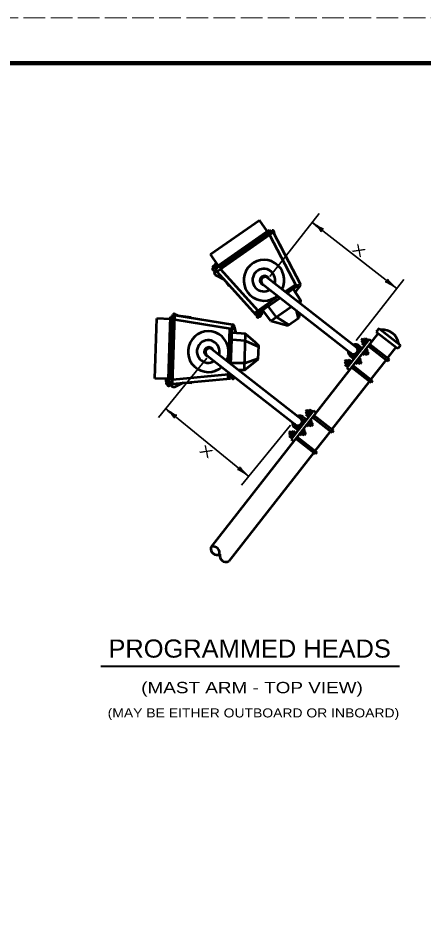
# Model space of a CAD drawing. Extents: x -286 to 394, y -156 to 284.
# Drawn here: x 126.4 to 216, y 87.7 to 284.5 of the extents above; entities that cross this region are included whole.
import ezdxf
from ezdxf.enums import TextEntityAlignment as Align

# ---------------------------------------------------------------- set-up
doc = ezdxf.new("R2010")
doc.units = 0
doc.header["$LTSCALE"] = 0.8
doc.linetypes.add('LONG_DASHED', pattern=[7.5, 6, -1.5])
doc.layers.add('1', color=7, linetype='Continuous', lineweight=53)
doc.layers.add('61', color=7, linetype='Continuous', lineweight=35)

msp = doc.modelspace()

# ---------------------------------------------------------------- linework, layer by layer
at = {"layer": '1', "lineweight": 35}
for p, q in [((192.9885, 241.2487), (182.1, 227.312)), ((191.4423, 239.2697), (210.1276, 224.6712)), ((211.6737, 226.6502), (201.1274, 213.1514)), ((157.4704, 196.1745), (168.1396, 209.2607)), ((159.0574, 198.121), (177.4352, 183.1374)), ((175.8484, 181.1909), (186.673, 194.4676))]:
    msp.add_line(p, q, dxfattribs=at)
at = {"layer": '1'}
for p, q in [((168.9452, 232.223), (179.8082, 239.7817)), ((181.5218, 237.3192), (179.8082, 239.7817)), ((170.2889, 228.3437), (182.8359, 237.0743)), ((170.6522, 229.7562), (181.9386, 237.6095)), ((171.143, 229.4887), (182.6347, 237.4847)), ((181.9386, 237.6095), (182.2242, 237.1989)), ((182.0084, 236.4987), (187.9568, 225.1043)), ((182.8359, 237.0743), (188.7847, 225.6803)), ((182.9205, 237.3707), (183.1277, 236.5162)), ((183.1277, 236.5162), (184.6073, 233.9458)), ((170.6587, 229.7608), (168.9452, 232.223)), ((169.8214, 229.2523), (169.5507, 229.1807)), ((170.2569, 229.0472), (169.5811, 229.3725)), ((170.3805, 229.2647), (169.6897, 229.5973)), ((169.9717, 229.1781), (169.8678, 228.9185)), ((169.9559, 229.4749), (169.8867, 229.7459)), ((170.0832, 229.4082), (170.2589, 229.6254)), ((170.3699, 228.4001), (179.0186, 218.8265)), ((171.1457, 228.9399), (179.4239, 219.7762)), ((170.1608, 227.5875), (172.0078, 226.614)), ((172.0078, 226.614), (173.0461, 225.1295)), ((181.4162, 227.1339), (201.3163, 211.5916)), ((180.3407, 225.7569), (200.2382, 210.2128)), ((185.4593, 223.9762), (187.7235, 225.5517)), ((185.8721, 223.6538), (187.9568, 225.1043)), ((188.8565, 222.0757), (187.2297, 224.5965)), ((188.5697, 225.0199), (187.6993, 223.869)), ((178.5965, 219.2007), (183.9578, 222.9313)), ((178.9342, 218.8265), (184.3704, 222.6089)), ((186.2382, 223.3678), (185.9982, 223.7399)), ((183.5209, 218.3632), (181.7223, 220.7643)), ((182.2897, 217.5062), (186.8448, 220.6758)), ((159.6772, 204.6498), (160.1542, 218.3912)), ((160.1542, 218.3912), (160.654, 218.3738)), ((160.1853, 204.8822), (160.6713, 218.8738)), ((160.5902, 203.5123), (161.1204, 218.7888)), ((160.9338, 219.0342), (161.7422, 218.6879)), ((161.1204, 218.7888), (173.8066, 216.7227)), ((161.7422, 218.6879), (164.6864, 218.332)), ((179.5824, 218.8785), (179.3481, 218.7266)), ((179.3996, 219.1328), (179.849, 218.5328)), ((179.5997, 219.2823), (180.0494, 218.6826)), ((179.6849, 218.7447), (179.6668, 218.4657)), ((179.7873, 219.0319), (179.9663, 219.2463)), ((179.877, 218.9202), (180.1561, 218.9043)), ((182.2897, 217.5062), (180.4912, 219.9077)), ((182.2897, 217.5062), (185.5074, 219.7455)), ((187.925, 219.832), (188.3123, 218.0422)), ((188.6141, 219.2937), (188.5174, 218.1855)), ((156.6793, 204.7616), (157.1387, 217.9876)), ((160.1368, 217.8837), (157.1387, 217.9876)), ((161.0853, 217.7815), (173.7717, 215.7147)), ((182.2897, 217.5062), (186.0552, 216.4717)), ((183.5209, 218.3632), (186.2604, 216.6146)), ((186.0552, 216.4717), (188.5174, 218.1855)), ((206.0048, 214.7497), (169.0651, 167.469)), ((173.1147, 211.2112), (173.2738, 215.7961)), ((173.6198, 211.3482), (173.7717, 215.7147)), ((176.7353, 214.6199), (173.7425, 214.8283)), ((174.2065, 216.1548), (174.6062, 214.7682)), ((206.2262, 215.8456), (205.6107, 215.0575)), ((205.6107, 215.0575), (210.3388, 211.3637)), ((206.2262, 215.8456), (210.9543, 212.1517)), ((176.6834, 213.1202), (173.6901, 213.3291)), ((176.6834, 213.1204), (179.6382, 211.767)), ((178.8171, 212.7587), (179.6463, 212.0172)), ((202.5814, 213.617), (202.2736, 213.223)), ((202.2736, 213.223), (203.2587, 212.4534)), ((203.2556, 213.6677), (202.3876, 212.5566)), ((202.3876, 212.5566), (202.9786, 212.0949)), ((202.6028, 213.4416), (202.4489, 213.2446)), ((202.7784, 213.4631), (202.4706, 213.0691)), ((202.5814, 213.617), (203.5666, 212.8474)), ((202.7999, 213.2877), (202.646, 213.0907)), ((203.2556, 213.6677), (203.8466, 213.2061)), ((204.0283, 213.4384), (204.6195, 212.9766)), ((169.1036, 211.3732), (189.0034, 195.8311)), ((173.0142, 208.3189), (173.1145, 211.2112)), ((173.5016, 207.9382), (173.62, 211.3482)), ((176.4579, 206.6245), (176.6504, 212.1706)), ((176.4579, 206.6245), (176.5937, 210.5425)), ((179.5427, 209.0189), (179.6463, 212.0172)), ((201.5034, 211.596), (202.1774, 211.0693)), ((201.7392, 212.0463), (202.4852, 211.4634)), ((202.7685, 210.6075), (203.5565, 209.9918)), ((203.7167, 211.009), (202.9162, 209.9844)), ((203.0763, 211.0015), (203.8643, 210.3858)), ((203.3227, 211.3167), (203.7167, 211.009)), ((203.6672, 210.5398), (203.3594, 210.1458)), ((203.8499, 211.9916), (208.1839, 208.6057)), ((204.1577, 212.3856), (208.4917, 208.9997)), ((209.9447, 211.6715), (208.0977, 209.3075)), ((210.9543, 212.1517), (210.3388, 211.3637)), ((168.0279, 209.9964), (187.9253, 194.4524)), ((176.4579, 206.6245), (179.5427, 209.0189)), ((176.5097, 208.1238), (179.5513, 209.2689)), ((198.8875, 208.889), (198.5797, 208.495)), ((199.5617, 208.9398), (198.6937, 207.8286)), ((198.9089, 208.7136), (198.755, 208.5166)), ((199.0845, 208.7351), (198.7767, 208.3411)), ((198.8875, 208.889), (199.8727, 208.1193)), ((199.106, 208.5597), (198.9521, 208.3627)), ((200.5653, 209.0058), (199.1032, 207.1342)), ((199.5617, 208.9398), (200.1527, 208.478)), ((199.8985, 209.6809), (200.6402, 209.1016)), ((199.9195, 210.462), (200.0032, 210.3228)), ((200.2063, 210.0749), (200.9479, 209.4956)), ((201.2312, 208.6398), (202.0193, 208.0244)), ((202.1793, 209.0413), (201.379, 208.0169)), ((201.5391, 209.0338), (202.327, 208.4183)), ((201.7853, 209.3491), (202.1793, 209.0413)), ((202.1299, 208.5722), (201.8222, 208.1783)), ((202.5222, 210.2922), (202.9162, 209.9844)), ((203.4762, 210.4987), (203.3531, 210.341)), ((203.6733, 210.3448), (203.5502, 210.1871)), ((203.8643, 210.3858), (203.5565, 209.9918)), ((207.7899, 208.9135), (204.4038, 204.5794)), ((208.4917, 208.9997), (208.1839, 208.6057)), ((176.5097, 208.1238), (173.5097, 208.1229)), ((176.4579, 206.6245), (175.184, 206.6242)), ((198.5797, 208.495), (199.5649, 207.7253)), ((198.6937, 207.8286), (199.2848, 207.3668)), ((199.1032, 207.1342), (199.6942, 206.6725)), ((200.1559, 207.2635), (204.49, 203.8776)), ((200.4638, 207.6576), (204.7978, 204.2716)), ((200.985, 208.3247), (201.379, 208.0169)), ((201.939, 208.5311), (201.8159, 208.3735)), ((202.1361, 208.3772), (202.013, 208.2196)), ((202.327, 208.4183), (202.0193, 208.0244)), ((159.6773, 204.6577), (156.6793, 204.7616)), ((160.5935, 203.6112), (173.3922, 204.7927)), ((160.6263, 204.5557), (172.9232, 205.6907)), ((172.8902, 204.7463), (172.9393, 206.1596)), ((173.3922, 204.7927), (173.4265, 205.779)), ((173.4237, 205.2858), (174.0577, 205.2859)), ((173.424, 205.5356), (173.7378, 205.5358)), ((173.7368, 205.2798), (173.718, 205.0011)), ((173.9054, 205.2817), (174.1179, 205.0999)), ((159.485, 203.9238), (159.2266, 204.0307)), ((159.9078, 204.1377), (159.2275, 203.784)), ((160.0078, 203.9083), (159.3424, 203.5623)), ((159.5826, 203.6827), (159.4777, 203.4232)), ((159.6147, 203.9857), (159.5462, 204.2565)), ((159.7321, 203.7585), (159.8777, 203.5198)), ((161.1188, 202.9567), (163.005, 203.8518)), ((163.005, 203.8518), (164.8156, 203.7934)), ((204.096, 204.1854), (195.7846, 193.5472)), ((204.7978, 204.2716), (204.49, 203.8776)), ((190.2685, 197.8566), (189.9607, 197.4626)), ((189.9607, 197.4626), (190.9458, 196.693)), ((190.9427, 197.9073), (190.0747, 196.7962)), ((190.0747, 196.7962), (190.6657, 196.3345)), ((190.2899, 197.6812), (190.136, 197.4842)), ((190.4655, 197.7027), (190.1577, 197.3087)), ((190.2685, 197.8566), (191.2537, 197.087)), ((190.487, 197.5272), (190.3331, 197.3303)), ((190.9427, 197.9073), (191.5337, 197.4457)), ((191.7154, 197.678), (192.3063, 197.2164)), ((189.1905, 195.8356), (189.8645, 195.3089)), ((189.4262, 196.2859), (190.1723, 195.703)), ((190.4556, 194.8471), (191.2436, 194.2314)), ((191.4038, 195.2486), (190.6033, 194.224)), ((190.7634, 195.2411), (191.5514, 194.6254)), ((191.0097, 195.5563), (191.4038, 195.2486)), ((191.3543, 194.7794), (191.0465, 194.3854)), ((191.537, 196.2312), (195.871, 192.8452)), ((191.8448, 196.6252), (196.1788, 193.2392)), ((186.5746, 193.1286), (186.2668, 192.7346)), ((187.2488, 193.1793), (186.3808, 192.0682)), ((186.596, 192.9532), (186.4421, 192.7562)), ((186.7716, 192.9747), (186.4638, 192.5807)), ((186.5746, 193.1286), (187.5598, 192.3589)), ((188.2524, 193.2454), (186.7902, 191.3738)), ((187.2488, 193.1793), (187.8398, 192.7176)), ((187.5856, 193.9205), (188.3272, 193.3412)), ((187.8934, 194.3145), (188.635, 193.7352)), ((188.9183, 192.8794), (189.7064, 192.264)), ((189.8664, 193.2809), (189.0661, 192.2565)), ((189.2262, 193.2734), (190.0141, 192.6579)), ((189.4724, 193.5887), (189.8664, 193.2809)), ((189.817, 192.8118), (189.5093, 192.4179)), ((190.2093, 194.5318), (190.6033, 194.224)), ((191.1633, 194.7382), (191.0402, 194.5806)), ((191.3604, 194.5843), (191.2372, 194.4267)), ((191.5514, 194.6254), (191.2436, 194.2314)), ((195.4767, 193.1532), (192.0907, 188.8192)), ((196.1788, 193.2392), (195.871, 192.8452)), ((186.2668, 192.7346), (187.252, 191.9649)), ((186.3808, 192.0682), (186.9718, 191.6064)), ((186.7931, 192.7993), (186.6392, 192.6022)), ((186.7902, 191.3738), (187.381, 190.9123)), ((187.843, 191.5031), (192.1771, 188.1172)), ((188.1509, 191.8972), (192.4849, 188.5112)), ((188.6721, 192.5642), (189.0661, 192.2565)), ((189.6261, 192.7707), (189.503, 192.6131)), ((189.8232, 192.6167), (189.7001, 192.4592)), ((190.0141, 192.6579), (189.7064, 192.264)), ((191.7827, 188.4253), (173.0051, 164.3907)), ((192.4849, 188.5112), (192.1771, 188.1172))]:
    msp.add_line(p, q, dxfattribs=at)
at = {"layer": '1', "lineweight": 40}
msp.add_line((144.7021, 141.212), (210.74, 141.212), dxfattribs=at)
at = {"layer": '1'}
for points in [[(170.6522, 229.7562), (169.8256, 228.2606), (170.2889, 228.3437)], [(188.3468, 221.721), (188.8565, 222.0757), (188.7951, 221.3709)], [(176.6505, 212.1706), (176.7353, 214.6199), (178.817, 212.7586)], [(204.0283, 213.4384), (202.5662, 211.5669), (200.5653, 209.0058)], [(159.6772, 204.6498), (160.379, 203.0917), (160.5902, 203.5123)], [(191.7154, 197.678), (190.2532, 195.8065), (188.2524, 193.2454)]]:
    msp.add_lwpolyline(points, dxfattribs=at)
for centre in [(182.6388, 237.248), (188.3776, 225.3079), (160.8632, 218.7351), (173.8608, 216.1736)]:
    msp.add_circle(centre, 0.1017, dxfattribs=at)
for centre, radius, start, end in [((182.7109, 237.2676), 0.2301, 302.89292, 109.35881), ((180.8013, 226.4584), 4.5, 333.68871, 311.29261), ((169.6271, 228.9502), 0.243, 108.32387, 352.5212), ((169.6268, 229.489), 0.1254, 59.95241, 248.62496), ((170.4196, 228.1365), 0.6069, 168.18066, 244.76157), ((170.1125, 229.8089), 0.2347, 308.58522, 195.64631), ((171.0092, 229.827), 0.364, 191.23275, 291.55987), ((180.7701, 226.5032), 2.5, 342.98256, 302.06743), ((180.8989, 226.4279), 1.0052, 23.95779, 262.9292), ((181.0541, 226.3131), 0.8972, 66.19313, 220.65033), ((188.3191, 225.4666), 0.5121, 224.97004, 24.69248), ((160.8908, 218.8046), 0.2301, 356.07364, 162.53953), ((179.4259, 218.4962), 0.243, 108.60971, 352.80704), ((179.9546, 218.6), 0.1254, 212.50594, 41.17849), ((180.1747, 219.1382), 0.2347, 265.48459, 152.54568), ((173.6988, 216.2219), 0.5121, 278.15075, 77.87319), ((168.4964, 210.6907), 4.5, 334.34216, 311.30255), ((206.9745, 211.9302), 3.6248, 8.39612, 95.60566), ((168.4647, 210.7351), 2.5, 343.63601, 302.72088), ((168.5943, 210.6613), 1.0052, 24.61124, 263.58265), ((168.7508, 210.5483), 0.8972, 66.84658, 221.30378), ((200.5605, 210.6003), 1.133, 168.40396, 234.24561), ((200.7734, 210.9049), 1.0052, 202.49407, 81.46547), ((200.6215, 211.024), 0.8972, 244.77294, 39.23013), ((201.0124, 211.1823), 1.133, 49.4358, 115.27744), ((159.8344, 204.978), 0.364, 244.41346, 344.74058), ((173.9491, 204.9253), 0.243, 161.79042, 45.98775), ((159.3115, 204.2492), 0.2347, 1.76594, 248.82702), ((159.2766, 203.6687), 0.1254, 113.13313, 301.80568), ((159.7081, 203.3461), 0.243, 161.50458, 45.70191), ((160.8344, 203.4928), 0.6069, 221.36137, 297.94229), ((188.2476, 194.8399), 1.133, 168.40396, 234.24561), ((188.4605, 195.1445), 1.0052, 202.49407, 81.46547), ((188.3085, 195.2636), 0.8972, 244.77294, 39.23013), ((188.6995, 195.4219), 1.133, 49.4358, 115.27744), ((170.4231, 167.1768), 1.3891, 167.85849, 296.14028), ((169.5278, 166.2058), 1.4466, 343.66244, 103.21923), ((172.3723, 165.6111), 1.3747, 166.59364, 297.40514)]:
    msp.add_arc(centre, radius, start, end, dxfattribs=at)
at = {"layer": '1', "lineweight": 35}
for centre, major_axis, ratio, start_param, end_param in [((192.195, 238.4132), (1.276, -1.2198), 0.07063, 6.28230741, 8.55970261), ((192.195, 238.4132), (1.276, -1.2198), 0.07063, 6.28230741, 8.55970261), ((192.4723, 238.8157), (-1.5033, 0.9763), 0.122415, 0.89635335, 3.14159265), ((192.4723, 238.8157), (-1.5033, 0.9763), 0.122415, 0.89635335, 3.14159265), ((209.3749, 225.5278), (-1.276, 1.2198), 0.07063, 6.28230741, 8.55970261), ((209.3749, 225.5278), (-1.276, 1.2198), 0.07063, 6.28230741, 8.55970261), ((209.0976, 225.1253), (1.5033, -0.9763), 0.122415, 0.89635335, 3.14159265), ((209.0976, 225.1253), (1.5033, -0.9763), 0.122415, 0.89635335, 3.14159265), ((159.7921, 197.249), (1.2503, -1.246), 0.07063, 6.28230741, 8.55970261), ((159.7921, 197.249), (1.2503, -1.246), 0.07063, 6.28230741, 8.55970261), ((160.0777, 197.6456), (-1.4827, 1.0074), 0.122415, 0.89635335, 3.14159265), ((160.0777, 197.6456), (-1.4827, 1.0074), 0.122415, 0.89635335, 3.14159265), ((176.7005, 184.0095), (-1.2503, 1.246), 0.07063, 6.28230741, 8.55970261), ((176.7005, 184.0095), (-1.2503, 1.246), 0.07063, 6.28230741, 8.55970261), ((176.4149, 183.6128), (1.4827, -1.0074), 0.122415, 0.89635335, 3.14159265), ((176.4149, 183.6128), (1.4827, -1.0074), 0.122415, 0.89635335, 3.14159265)]:
    msp.add_ellipse(centre, major_axis=major_axis, ratio=ratio, start_param=start_param, end_param=end_param, dxfattribs=at)
at = {"layer": '61', "linetype": 'LONG_DASHED', "lineweight": 13}
msp.add_line((-286.3491, 284.4627), (393.6709, 284.4627), dxfattribs=at)
at = {"layer": '61', "lineweight": 158}
msp.add_lwpolyline([(382.6909, 274.4627), (-256.3491, 274.4627), (-256.3491, -145.5572)], dxfattribs=at)

# ---------------------------------------------------------------- texts
at = {"layer": '1', "width": 1.55}
for p in [(201.1897, 232.2294), (167.4801, 187.8125)]:
    msp.add_text('X', height=2, rotation=324.999, dxfattribs=at).set_placement(p, align=Align.CENTER)
at = {"layer": '1'}
for s, height, width, p in [('PROGRAMMED HEADS', 4, 1.05, (177.6243, 143.0893)), ('(MAST ARM - TOP VIEW)', 2.5, 1.25, (178.1489, 135.2221)), ('(MAY BE EITHER OUTBOARD OR INBOARD)', 2, 1.15, (178.46, 129.8698))]:
    msp.add_text(s, height=height, dxfattribs=dict(at, width=width)).set_placement(p, align=Align.CENTER)

doc.saveas('drawing.dxf')
